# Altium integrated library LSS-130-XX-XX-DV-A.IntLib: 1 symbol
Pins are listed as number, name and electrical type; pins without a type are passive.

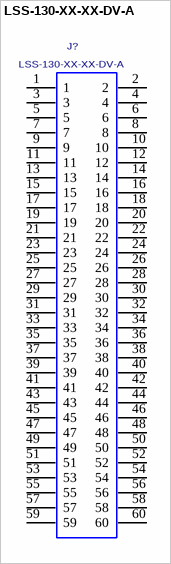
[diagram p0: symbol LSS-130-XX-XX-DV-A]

## LSS-130-XX-XX-DV-A
designator J?
0.635MM TERMINAL/SOCKET COMB, 60 PINS.; MANUFACTURER: SAMTEC
footprint LSS-130-XX-XX-DV-A
pins: 1, 2, 3, 4, 5, 6, 7, 8, 9, 10, 11, 12, 13, 14, 15, 16, 17, 18, 19, 20, 21, 22, 23, 24, 25, 26, 27, 28, 29, 30, 31, 32, 33, 34, 35, 36, 37, 38, 39, 40, 41, 42, 43, 44, 45, 46, 47, 48, 49, 50, 51, 52, 53, 54, 55, 56, 57, 58, 59, 60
